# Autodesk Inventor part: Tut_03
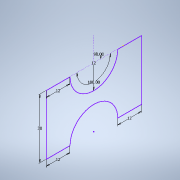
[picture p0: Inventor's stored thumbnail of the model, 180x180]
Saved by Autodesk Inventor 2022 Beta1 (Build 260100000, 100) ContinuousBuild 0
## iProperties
Created: 2019-02
Part Number: Tut_03
Material: Generic
Document SubType Name: Modeling
Designer: LENOVO-CADCIM
Density: 1 g/cm^3
Appearance: Default
Author: LENOVO-CADCIM
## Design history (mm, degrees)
sketch "Sketch1"
  geometry: L1 (0, 15)-(0, 3); L2 (0, 15)-(12, 15); L3 (0, 15)-(0, 27); L4 (0, 27)-(0, 39); L5 (0, 39)-(-30, 39); L6 (-30, 39)-(-30, 27); L7 (-30, 3)-(-30, -9); L8 (-30, -9)-(0, -9); L9 (0, -9)-(0, 3); A1 r 12 centre (0, 15) between (0, 27) and (0, 3); A2 r 12 centre (-30, 15) between (-30, 3) and (-30, 27); 1 further point
  constraints: 18 end point, 5 perpendicular, 5 point on circle, 4 point on line, 2 centre point, 1 horizontal, 1 vertical
  dimensions: "d0" = 12 radius of A1; "d1" = 90 deg angle of L1 L2; "d2" = 180 deg angle of L1 L3; "d3" = 12 distance of L4.start L4.end; "d4" = 30 distance of L4.end L5.end; "d5" = 12 distance of L5.end L6.end; "d6" = 12 distance of L7.start L7.end
